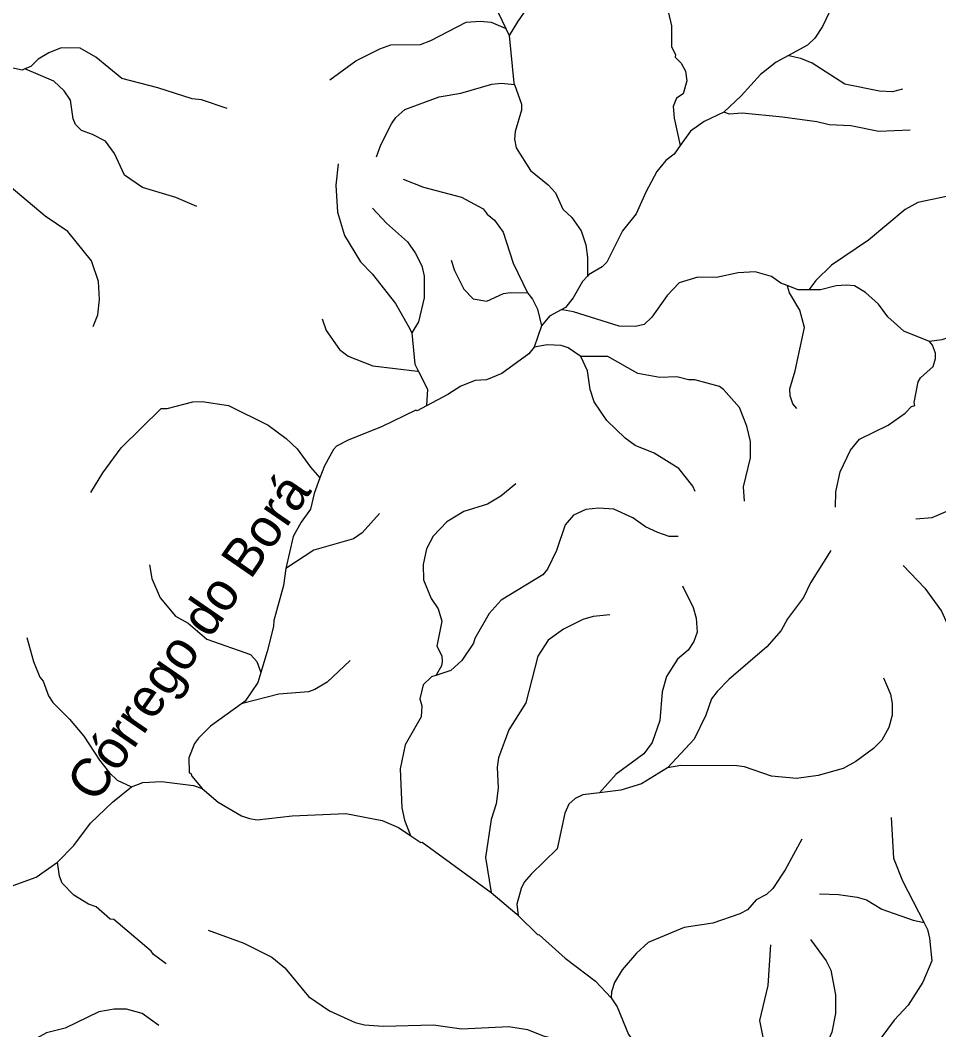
# Model space of a CAD drawing. Extents: x 393 to 446.6, y 8175.5 to 8231.
# Drawn here: x 395.927 to 399.745, y 8222.049 to 8226.244 of the extents above; entities that cross this region are included whole.
import ezdxf
from ezdxf.enums import TextEntityAlignment as Align

# ---------------------------------------------------------------- set-up
doc = ezdxf.new("R2010")
doc.units = 0
doc.header["$LTSCALE"] = 0.064
doc.linetypes.add('LONG_DASHED', pattern=[7.5, 6, -1.5])
doc.layers.add('61', color=7, linetype='Continuous')
doc.layers.add('7', color=7, linetype='Continuous', lineweight=25)
doc.layers.add('9', color=7, linetype='LONG_DASHED', lineweight=25)

msp = doc.modelspace()

# ---------------------------------------------------------------- linework, layer by layer
at = {"layer": '7'}
for p, q in [((397.9459, 8226.2097), (397.9601, 8226.1809)), ((398.0934, 8224.9736), (398.0627, 8224.8861))]:
    msp.add_line(p, q, dxfattribs=at)
for points in [[(397.9481, 8226.7774), (397.8956, 8226.744), (397.8375, 8226.6891), (397.7939, 8226.6374), (397.768, 8226.5631), (397.768, 8226.4985), (397.7729, 8226.4824), (397.8504, 8226.3564), (397.9117, 8226.2789), (397.9459, 8226.2097)], [(398.5237, 8226.6023), (398.4947, 8226.5341), (398.4963, 8226.4533), (398.5334, 8226.3677), (398.5593, 8226.3386), (398.5868, 8226.3209), (398.6206, 8226.2805), (398.6336, 8226.2208), (398.6336, 8226.1336), (398.6513, 8226.1013), (398.6497, 8226.09), (398.6739, 8226.0657), (398.6917, 8226.0318), (398.6982, 8225.9915), (398.682, 8225.9382), (398.6546, 8225.9204), (398.6416, 8225.8849), (398.6449, 8225.8365), (398.6704, 8225.7237)], [(399.3353, 8226.502), (399.3182, 8226.4307), (399.3182, 8226.3726), (399.2892, 8226.2757), (399.2617, 8226.2176), (399.2294, 8226.1691), (399.1987, 8226.14), (399.1203, 8226.0969)], [(398.0342, 8226.2953), (397.9935, 8226.2378), (397.9601, 8226.1809)], [(397.2135, 8225.9967), (397.3224, 8226.0754), (397.4225, 8226.1255), (397.4677, 8226.1416), (397.5904, 8226.1433), (397.634, 8226.1594), (397.781, 8226.2353), (397.8391, 8226.2401), (397.8843, 8226.2353), (397.9433, 8226.2108), (397.9459, 8226.2097)], [(397.9601, 8226.1809), (397.9794, 8225.9825), (397.9815, 8225.9766)], [(399.1203, 8226.0969), (399.0695, 8226.069), (399.0034, 8226.0189), (398.9242, 8225.9301), (398.851, 8225.8619)], [(399.5946, 8225.9574), (399.5526, 8225.9469), (399.4991, 8225.9495), (399.3538, 8225.9785), (399.2181, 8226.0657), (399.1713, 8226.0851), (399.1221, 8226.0965), (399.1203, 8226.0969)], [(397.4076, 8225.6767), (397.4257, 8225.7267), (397.4709, 8225.8139), (397.4887, 8225.8397), (397.5258, 8225.8736), (397.6679, 8225.9252), (397.7584, 8225.9414), (397.8876, 8225.9786), (397.9263, 8225.9818), (397.9815, 8225.9766)], [(397.9815, 8225.9766), (398.0103, 8225.8946), (398.0103, 8225.8704), (397.9844, 8225.7816), (397.9812, 8225.7493), (397.9892, 8225.7138), (398.0474, 8225.6201), (398.1217, 8225.5603), (398.1524, 8225.5264), (398.183, 8225.4586), (398.2202, 8225.4247), (398.2589, 8225.3682), (398.2783, 8225.3101), (398.2848, 8225.2584), (398.2848, 8225.1808)], [(398.851, 8225.8619), (398.7692, 8225.8235), (398.7127, 8225.7831), (398.6704, 8225.7237)], [(399.6259, 8225.787), (399.4959, 8225.7815), (399.3796, 8225.8058), (399.2892, 8225.809), (399.2375, 8225.8219), (399.0954, 8225.8413), (398.9275, 8225.8574), (398.8758, 8225.8542), (398.851, 8225.8619)], [(398.6704, 8225.7237), (398.6449, 8225.6879), (398.611, 8225.6604), (398.5738, 8225.6152), (398.527, 8225.5297), (398.4866, 8225.4392), (398.4301, 8225.3682), (398.3655, 8225.239), (398.3462, 8225.2196), (398.2889, 8225.1853), (398.2848, 8225.1808)], [(397.2491, 8225.6467), (397.2384, 8225.5587), (397.2464, 8225.4457), (397.2755, 8225.3488), (397.3417, 8225.2406), (397.3902, 8225.1905), (397.4871, 8225.0662), (397.5403, 8224.9742), (397.5543, 8224.9445)], [(397.5192, 8225.5832), (397.6033, 8225.5506), (397.7616, 8225.5086), (397.852, 8225.4602), (397.8682, 8225.4376), (397.8988, 8225.4134), (397.9343, 8225.3633), (397.9763, 8225.2341), (398.0356, 8225.1109)], [(400.0972, 8225.4961), (400.025, 8225.5147), (399.8931, 8225.5232), (399.7769, 8225.5119), (399.6574, 8225.486), (399.6057, 8225.457), (399.4523, 8225.3294), (399.2989, 8225.226), (399.2343, 8225.1631), (399.2055, 8225.1243)], [(397.3921, 8225.4636), (397.4499, 8225.4005), (397.5371, 8225.323), (397.5694, 8225.2778), (397.5969, 8225.2229), (397.6066, 8225.1809), (397.6066, 8225.0904), (397.5823, 8224.9903), (397.5543, 8224.9445)], [(397.7183, 8225.2471), (397.7325, 8225.2035), (397.7713, 8225.126), (397.81, 8225.0856), (397.8665, 8225.0759), (397.936, 8225.1082), (397.9651, 8225.113), (398.0356, 8225.1109)], [(400.2849, 8225.2167), (400.2558, 8225.1759), (400.187, 8225.1098), (400.116, 8225.0533), (400.0352, 8225.008), (399.9965, 8224.9951), (399.9061, 8224.979), (399.7962, 8224.9289), (399.7575, 8224.916), (399.7059, 8224.9091)], [(399.1152, 8225.1413), (399.0881, 8225.1516), (399.0502, 8225.1792), (398.9823, 8225.1986), (398.9113, 8225.1938), (398.8209, 8225.1744), (398.7434, 8225.176), (398.6659, 8225.1534), (398.6158, 8225.1001), (398.5528, 8225.0097), (398.5206, 8224.979), (398.485, 8224.9709), (398.4172, 8224.9725), (398.2267, 8225.0323), (398.1807, 8225.04), (398.1758, 8225.0408)], [(398.2848, 8225.1808), (398.2644, 8225.1585), (398.225, 8225.0904), (398.1935, 8225.0504), (398.1758, 8225.0408)], [(399.1553, 8224.6304), (399.1379, 8224.6502), (399.1277, 8224.6835), (399.1261, 8224.7126), (399.1487, 8224.7869), (399.1874, 8224.9677), (399.168, 8225.0388), (399.1245, 8225.1114), (399.116, 8225.1388), (399.1152, 8225.1413)], [(399.2055, 8225.1243), (399.16, 8225.1243), (399.1152, 8225.1413)], [(399.7059, 8224.9091), (399.5992, 8224.9515), (399.533, 8225.0113), (399.4942, 8225.0646), (399.441, 8225.113), (399.3941, 8225.1405), (399.3603, 8225.1437), (399.3183, 8225.1405), (399.2537, 8225.1243), (399.2055, 8225.1243)], [(398.0356, 8225.1109), (398.0565, 8225.0853), (398.0765, 8225.0436), (398.0934, 8224.9736)], [(398.1758, 8225.0408), (398.1271, 8225.0144), (398.0934, 8224.9736)], [(397.1828, 8225.0029), (397.1991, 8224.9551), (397.2545, 8224.8757), (397.2901, 8224.8482), (397.3934, 8224.8078), (397.5788, 8224.7851), (397.583, 8224.7846)], [(397.5543, 8224.9445), (397.5671, 8224.8154), (397.583, 8224.7846)], [(398.0627, 8224.8861), (398.0405, 8224.8582), (397.9295, 8224.7755), (397.865, 8224.7497), (397.8181, 8224.7464), (397.7584, 8224.7238), (397.7051, 8224.6883), (397.6158, 8224.6419)], [(398.2569, 8224.846), (398.2041, 8224.8821), (398.175, 8224.8918), (398.1169, 8224.895), (398.0627, 8224.8861)], [(399.3162, 8224.22), (399.3173, 8224.284), (399.3344, 8224.367), (399.378, 8224.4574), (399.4151, 8224.5026), (399.5346, 8224.5608), (399.6057, 8224.6108), (399.6315, 8224.6383), (399.646, 8224.6431), (399.6428, 8224.656), (399.6589, 8224.7416), (399.6687, 8224.7578), (399.7219, 8224.8046), (399.7316, 8224.8385), (399.7316, 8224.8611), (399.7187, 8224.8934), (399.7059, 8224.9091)], [(398.9374, 8224.2462), (398.9339, 8224.3057), (398.963, 8224.4251), (398.963, 8224.493), (398.9468, 8224.5576), (398.9161, 8224.6351), (398.8499, 8224.7093), (398.8338, 8224.7222), (398.7305, 8224.7497), (398.7046, 8224.7497), (398.6562, 8224.7626), (398.5852, 8224.7594), (398.4947, 8224.7755), (398.3688, 8224.8466), (398.2569, 8224.846)], [(398.7329, 8224.2859), (398.7224, 8224.308), (398.6643, 8224.3815), (398.5625, 8224.4445), (398.4834, 8224.4768), (398.4414, 8224.5075), (398.3655, 8224.5801), (398.3122, 8224.6577), (398.2961, 8224.7094), (398.2848, 8224.7869), (398.2569, 8224.846)], [(397.583, 8224.7846), (397.6207, 8224.7113), (397.6159, 8224.6435), (397.6158, 8224.6419)], [(396.2203, 8224.2812), (396.2711, 8224.3638), (396.347, 8224.4671), (396.5134, 8224.6302), (396.5376, 8224.6302), (396.6442, 8224.6576), (396.6829, 8224.6592), (396.7927, 8224.6431), (396.9574, 8224.5607), (397.0333, 8224.5059), (397.0785, 8224.4623), (397.1334, 8224.3864), (397.1731, 8224.342)], [(397.6158, 8224.6419), (397.5764, 8224.6214), (397.571, 8224.6237), (397.429, 8224.5543), (397.2933, 8224.501), (397.2416, 8224.4735), (397.2287, 8224.4606), (397.1915, 8224.3929), (397.1731, 8224.342)], [(397.1731, 8224.342), (397.1496, 8224.2771), (397.1334, 8224.212), (397.0947, 8224.1587), (397.0624, 8224.099), (397.0319, 8223.9651)], [(397.9877, 8224.3179), (397.9247, 8224.2669), (397.8698, 8224.233), (397.7713, 8224.2023), (397.7002, 8224.1603), (397.6437, 8224.1006), (397.6162, 8224.0473), (397.6017, 8223.9827), (397.6033, 8223.9181), (397.6356, 8223.8406), (397.6647, 8223.7986), (397.6792, 8223.7469), (397.6582, 8223.6436), (397.6792, 8223.6032), (397.6808, 8223.579), (397.6776, 8223.5612), (397.6571, 8223.5248), (397.6552, 8223.5215)], [(398.6618, 8224.098), (398.6245, 8224.098), (398.577, 8224.1151), (398.5254, 8224.1393), (398.4737, 8224.1764), (398.3946, 8224.212), (398.33, 8224.2168), (398.2783, 8224.2103), (398.2267, 8224.1877), (398.1927, 8224.1474), (398.1556, 8224.0408), (398.1184, 8223.9633), (398.0991, 8223.9391), (397.9263, 8223.8341), (397.8762, 8223.7792), (397.8165, 8223.6743), (397.8116, 8223.6549), (397.7632, 8223.5838), (397.7164, 8223.5418), (397.6552, 8223.5215)], [(397.4206, 8224.1943), (397.3482, 8224.1134), (397.3127, 8224.0892), (397.148, 8224.0424), (397.0319, 8223.9651)], [(399.2966, 8224.041), (399.2117, 8223.9068), (399.1826, 8223.8454), (399.1164, 8223.7566), (399.0905, 8223.7082), (399.0308, 8223.6403), (398.8726, 8223.5047), (398.8241, 8223.4546), (398.7999, 8223.424), (398.7773, 8223.3562), (398.7288, 8223.256), (398.6173, 8223.1377)], [(396.4645, 8223.9805), (396.475, 8223.9235), (396.5085, 8223.8438), (396.5731, 8223.7679), (396.6248, 8223.7388), (396.7023, 8223.6727), (396.8838, 8223.6078), (396.9106, 8223.5799), (396.9276, 8223.5336)], [(397.0319, 8223.9651), (397.022, 8223.8955), (396.9816, 8223.7502), (396.98, 8223.7243), (396.9542, 8223.621), (396.9276, 8223.5336)], [(399.5969, 8223.9779), (399.6864, 8223.8841), (399.7559, 8223.7889), (399.7801, 8223.7356), (399.8043, 8223.6452), (399.8027, 8223.5467), (399.8107, 8223.4821), (399.8414, 8223.3497), (399.8979, 8223.1947), (399.9302, 8223.1398), (399.9658, 8223.1026), (400.0885, 8223.0025), (400.1321, 8222.9799), (400.2468, 8222.8894), (400.2903, 8222.8346), (400.3517, 8222.7393), (400.3824, 8222.7086), (400.4557, 8222.6604)], [(398.6797, 8223.8933), (398.724, 8223.8034), (398.7369, 8223.7599), (398.7401, 8223.7017), (398.7272, 8223.663), (398.703, 8223.6258), (398.6594, 8223.5886), (398.6126, 8223.5176), (398.5948, 8223.453), (398.5851, 8223.3335), (398.5544, 8223.2431), (398.5189, 8223.1962), (398.4043, 8223.1107), (398.3353, 8223.0337)], [(398.3778, 8223.773), (398.309, 8223.7663), (398.2654, 8223.7534), (398.1847, 8223.713), (398.1217, 8223.6678), (398.0781, 8223.6016), (398.028, 8223.4078), (397.9586, 8223.2948), (397.915, 8223.1785), (397.9101, 8223.1398), (397.9134, 8223.0526), (397.9053, 8222.988), (397.8843, 8222.9234), (397.8617, 8222.7651), (397.8846, 8222.6199)], [(395.9549, 8223.6794), (395.9821, 8223.579), (396.0095, 8223.5144), (396.0225, 8223.4982), (396.045, 8223.4369), (396.0628, 8223.4094), (396.1323, 8223.34), (396.192, 8223.269), (396.2566, 8223.1688), (396.2986, 8223.1172), (396.3309, 8223.0864), (396.3895, 8223.0579)], [(397.2982, 8223.5835), (397.2029, 8223.4934), (397.1512, 8223.4627), (397.1254, 8223.453), (397.0026, 8223.4433), (396.851, 8223.4041), (396.8466, 8223.403)], [(396.9276, 8223.5336), (396.9151, 8223.4925), (396.8627, 8223.4145), (396.8466, 8223.403)], [(397.6552, 8223.5215), (397.6373, 8223.5155), (397.6017, 8223.4821), (397.5888, 8223.424), (397.5969, 8223.3949), (397.5936, 8223.3497), (397.5274, 8223.2334), (397.5064, 8223.1333), (397.5129, 8222.9718), (397.5242, 8222.9202), (397.5499, 8222.8566), (397.5504, 8222.8554)], [(399.5156, 8223.5119), (399.5443, 8223.4434), (399.5508, 8223.4046), (399.5508, 8223.3562), (399.5378, 8223.3045), (399.5088, 8223.2528), (399.4733, 8223.2172), (399.4006, 8223.164), (399.3473, 8223.1349), (399.244, 8223.1058), (399.1536, 8223.0929), (399.0502, 8223.1026), (398.9372, 8223.1413), (398.9049, 8223.1462), (398.6723, 8223.1478), (398.6173, 8223.1377)], [(396.8466, 8223.403), (396.7184, 8223.3109), (396.6683, 8223.2609), (396.6522, 8223.2383), (396.628, 8223.1785), (396.6296, 8223.1171), (396.6361, 8223.1155), (396.6409, 8223.1026), (396.6839, 8223.0522)], [(398.6173, 8223.1377), (398.5092, 8223.0703), (398.4237, 8223.0445), (398.3353, 8223.0337)], [(396.3895, 8223.0579), (396.4375, 8223.0768), (396.515, 8223.08), (396.6474, 8223.0638), (396.6839, 8223.0522)], [(396.0818, 8222.7449), (396.15, 8222.8152), (396.2194, 8222.9072), (396.3115, 8222.9944), (396.3895, 8223.0579)], [(396.6839, 8223.0522), (396.7507, 8222.9944), (396.8476, 8222.9379), (396.8799, 8222.9266), (396.9122, 8222.9217), (397.0576, 8222.9379), (397.2804, 8222.9476), (397.4322, 8222.9185), (397.5, 8222.8894), (397.5504, 8222.8554)], [(398.3353, 8223.0337), (398.2654, 8223.0251), (398.2331, 8223.0105), (398.2073, 8222.9863), (398.1911, 8222.9492), (398.1588, 8222.8006), (398.0506, 8222.6957), (398.0215, 8222.6618), (398.0086, 8222.636), (397.9909, 8222.5714), (397.9968, 8222.5241), (397.9968, 8222.524)], [(399.5465, 8222.9315), (399.5572, 8222.7619), (399.5944, 8222.6683), (399.6822, 8222.4958)], [(397.5504, 8222.8554), (397.5918, 8222.8275), (397.5985, 8222.8281), (397.8846, 8222.6199)], [(399.1755, 8222.8411), (399.1067, 8222.7135), (399.055, 8222.636), (399.0292, 8222.6117), (398.9856, 8222.5891), (398.9501, 8222.5471), (398.9178, 8222.531), (398.8064, 8222.4922), (398.6869, 8222.4744), (398.5367, 8222.4115), (398.4883, 8222.3679), (398.4285, 8222.2984), (398.3978, 8222.2452), (398.3849, 8222.2064), (398.3833, 8222.1817)], [(395.7923, 8222.6242), (395.8981, 8222.6488), (395.9934, 8222.6827), (396.0818, 8222.7449)], [(396.5344, 8222.3233), (396.4808, 8222.3617), (396.4713, 8222.376), (396.3164, 8222.5067), (396.3018, 8222.5083), (396.2437, 8222.56), (396.2114, 8222.5713), (396.15, 8222.6085), (396.1016, 8222.6585), (396.0902, 8222.6876), (396.0818, 8222.7449)], [(397.8846, 8222.6199), (397.9917, 8222.5291), (397.9968, 8222.524)], [(399.2496, 8222.6142), (399.328, 8222.6117), (399.4055, 8222.6004), (399.4442, 8222.5891), (399.5088, 8222.5503), (399.638, 8222.5051), (399.6779, 8222.4967), (399.6822, 8222.4958)], [(397.9968, 8222.524), (398.0768, 8222.4447), (398.0845, 8222.4438), (398.1927, 8222.3469), (398.3187, 8222.2516), (398.3833, 8222.1817)], [(399.6822, 8222.4958), (399.6977, 8222.4653), (399.7058, 8222.4293), (399.7155, 8222.3356), (399.6783, 8222.2468), (399.617, 8222.1515), (399.5589, 8222.0885), (399.4765, 8221.9771), (399.4313, 8221.9302), (399.3861, 8221.898), (399.3538, 8221.8786), (399.3118, 8221.8641), (399.2343, 8221.8527), (399.1511, 8221.8568)], [(396.709, 8222.4624), (396.8573, 8222.4083), (396.9736, 8222.3501), (397.0268, 8222.3065), (397.1253, 8222.187), (397.2126, 8222.1273), (397.3192, 8222.0788), (397.3579, 8222.0691), (397.4354, 8222.0643), (397.6453, 8222.0691), (397.7616, 8222.053), (397.9586, 8222.0627), (398.0361, 8222.0497), (398.1007, 8222.0239), (398.1911, 8222.0029), (398.3116, 8221.9982)], [(399.0458, 8222.4023), (399.034, 8222.2323), (399.0001, 8222.0869), (399.0211, 8221.9836), (399.0211, 8221.9319), (399.0114, 8221.8802), (398.9825, 8221.8078), (398.982, 8221.8066)], [(399.2115, 8222.4241), (399.2763, 8222.3356), (399.2956, 8222.2968), (399.315, 8222.1935), (399.315, 8222.116), (399.3005, 8222.0385), (399.2795, 8221.99), (399.2391, 8221.9367), (399.1511, 8221.8568)], [(398.3833, 8222.1817), (398.4089, 8222.1444), (398.4559, 8222.0288), (398.4939, 8221.9794)], [(396.5032, 8222.0674), (396.4342, 8222.116), (396.3697, 8222.1353), (396.318, 8222.1353), (396.2534, 8222.124), (396.1145, 8222.0562), (396.037, 8222.0368), (395.9789, 8222.0045), (395.8303, 8221.906), (395.7431, 8221.8414), (395.6946, 8221.7963), (395.58, 8221.6574), (395.5251, 8221.5973)]]:
    msp.add_lwpolyline(points, dxfattribs=at)
at = {"layer": '9'}
for points in [[(396.7876, 8225.8775), (396.6802, 8225.9137), (396.6416, 8225.9175), (396.4994, 8225.9626), (396.3497, 8226.0014), (396.2419, 8226.09), (396.1768, 8226.1285), (396.0973, 8226.129), (396.0459, 8226.1083), (396.0017, 8226.0822), (395.9709, 8226.0523), (395.9466, 8226.0414)], [(396.2306, 8224.9711), (396.25, 8225.0194), (396.2564, 8225.0835), (396.2532, 8225.1581), (396.2239, 8225.244), (396.1255, 8225.3665), (396.0305, 8225.4295), (395.8555, 8225.5785), (395.8074, 8225.6432), (395.7931, 8225.6846), (395.8203, 8225.7858), (395.819, 8225.8392), (395.8029, 8225.8657), (395.7979, 8225.8915), (395.8032, 8225.9145), (395.822, 8225.9481), (395.8332, 8226.0003), (395.8202, 8226.0522)], [(395.9466, 8226.0414), (395.9361, 8226.0367), (395.8718, 8226.05), (395.8202, 8226.0522)], [(396.6614, 8225.4694), (396.5747, 8225.5067), (396.435, 8225.5487), (396.3613, 8225.5999), (396.3198, 8225.6904), (396.2816, 8225.7416), (396.2283, 8225.7697), (396.1819, 8225.7858), (396.1569, 8225.8101), (396.147, 8225.8339), (396.1361, 8225.9118), (396.1099, 8225.9506), (396.0667, 8225.9901), (395.9466, 8226.0414)], [(399.6501, 8224.1719), (399.7171, 8224.178), (399.7849, 8224.2071), (400.0142, 8224.3492), (400.0901, 8224.3815), (400.3905, 8224.4461), (400.4777, 8224.4687), (400.5068, 8224.4816)]]:
    msp.add_lwpolyline(points, dxfattribs=at)

# ---------------------------------------------------------------- texts
at = {"layer": '61'}
msp.add_text('Córrego do Borá', height=0.16, rotation=55.377, dxfattribs=at).set_placement((396.6916, 8223.6369), align=Align.CENTER)

doc.saveas('drawing.dxf')
